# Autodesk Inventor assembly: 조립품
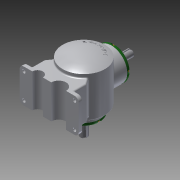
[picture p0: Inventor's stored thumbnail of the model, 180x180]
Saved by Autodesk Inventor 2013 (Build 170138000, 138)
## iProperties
Created: 2018-08
Part Number: 조립품
Document SubType Name: Assembly
Designer: Administrator
Author: Administrator
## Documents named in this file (14)
- C:\Users\Administrator\Desktop\480808V1016\조립품.iam
- C:\Users\Administrator\Desktop\480808V1016\본체.ipt
- C:\Users\Administrator\Desktop\480808V1016\480808V1016\메인 베벨기어.ipt
- C:\Users\Administrator\Desktop\480808V1016\480808V1016\메인 축.ipt
- 메인 축.ipt
- C:\Users\Administrator\Desktop\480808V1016\480808V1016\베어링 6203.ipt
- C:\Users\Administrator\Desktop\480808V1016\480808V1016\볼트 M4.ipt
- C:\Users\Administrator\Desktop\480808V1016\480808V1016\서브 베벨기어.ipt
- C:\Users\Administrator\Desktop\480808V1016\480808V1016\서브 축.ipt
- 서브 축.ipt
- C:\Users\Administrator\Desktop\480808V1016\480808V1016\오일실 17 32 8.ipt
- C:\Users\Administrator\Desktop\480808V1016\480808V1016\커버.ipt
- C:\Users\Administrator\Desktop\480808V1016\480808V1016\키 4x4.ipt
- C:\Users\Administrator\Desktop\480808V1016\480808V1016\키 5x5.ipt
